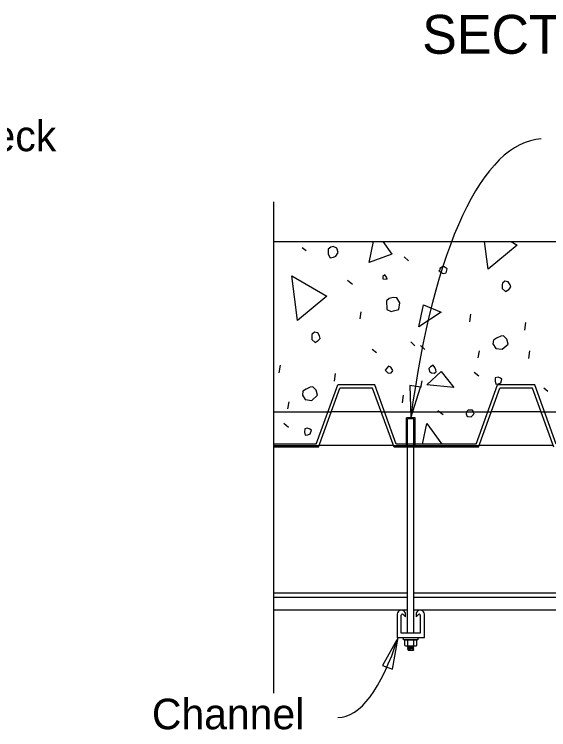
# Model space of a CAD drawing. Extents: x 112544 to 112597.1, y 111084 to 111107.1.
# Drawn here: x 112556.46 to 112559.102, y 111092.028 to 111095.563 of the extents above; entities that cross this region are included whole.
import ezdxf

# ---------------------------------------------------------------- set-up
doc = ezdxf.new("R2010")
doc.units = 0
for name, color, linetype in [('Dimension', 7, 'Continuous'), ('Lighting', 7, 'Continuous'), ('Miscellaneous', 7, 'Continuous'), ('SteelGirder', 7, 'Continuous'), ('SteelGirder_h', 7, 'Continuous'), ('SupstrConc', 7, 'Continuous'), ('TextStructures', 7, 'Continuous')]:
    doc.layers.add(name, color=color, linetype=linetype)

msp = doc.modelspace()

# ---------------------------------------------------------------- linework, layer by layer
at = {"layer": 'Dimension'}
msp.add_lwpolyline([(112557.7434, 111092.2077), (112557.7434, 111094.6352)], dxfattribs=at)
for points in [[(112558.4199, 111093.5693), (112558.4676, 111093.7204), (112558.4152, 111093.7277)], [(112558.3574, 111092.4831), (112558.2792, 111092.3454), (112558.3289, 111092.3273)]]:
    msp.add_lwpolyline(points, close=True, dxfattribs=at)
for centre, major_axis, ratio, start_param, end_param in [((112559.2223, 111092.0282), (0.1574, -2.9184), 0.2923, 3.141622, 4.140363), ((112558.0464, 111093.7554), (-0.0129, 1.6676), 0.280094, 3.141615, 3.84244)]:
    msp.add_ellipse(centre, major_axis=major_axis, ratio=ratio, start_param=start_param, end_param=end_param, dxfattribs=at)
at = {"layer": 'Lighting'}
for p, q in [((112558.4043, 111092.7018), (112557.7434, 111092.7018)), ((112559.1907, 111092.7018), (112558.4355, 111092.7018)), ((112558.4043, 111092.681), (112557.7434, 111092.681)), ((112559.2211, 111092.681), (112558.4355, 111092.681)), ((112558.4043, 111092.6185), (112557.7434, 111092.6185)), ((112558.3522, 111092.5977), (112558.3522, 111092.4831)), ((112558.373, 111092.5039), (112558.373, 111092.5929)), ((112558.3819, 111092.5966), (112558.3938, 111092.5847)), ((112558.3938, 111092.6026), (112558.3917, 111092.6069)), ((112558.3938, 111092.5847), (112558.3938, 111092.6026)), ((112560.3522, 111092.6185), (112558.4355, 111092.6185)), ((112558.4481, 111092.6069), (112558.446, 111092.6026)), ((112558.446, 111092.6026), (112558.446, 111092.5847)), ((112558.446, 111092.5847), (112558.4579, 111092.5966)), ((112558.4668, 111092.5929), (112558.4668, 111092.5039)), ((112558.4876, 111092.4831), (112558.4876, 111092.5977)), ((112558.4668, 111092.5039), (112558.373, 111092.5039)), ((112558.3522, 111092.4831), (112558.4876, 111092.4831))]:
    msp.add_line(p, q, dxfattribs=at)
for centre, radius, start, end in [((112558.373, 111092.5977), 0.0208, 26.1794, 179.9999), ((112558.3782, 111092.5929), 0.0052, 45, 180), ((112558.4668, 111092.5977), 0.0208, 0.0001, 153.8206), ((112558.4616, 111092.5929), 0.0052, 360, 135)]:
    msp.add_arc(centre, radius, start, end, dxfattribs=at)
at = {"layer": 'Miscellaneous'}
for p, q in [((112557.8828, 111094.4109), (112557.9025, 111094.3954)), ((112558.3869, 111094.3648), (112558.4079, 111094.3445)), ((112558.1075, 111094.2485), (112558.1309, 111094.2289)), ((112558.1689, 111094.0579), (112558.175, 111094.0932)), ((112558.7113, 111094.0428), (112558.7167, 111094.0805)), ((112558.9837, 111094.0019), (112558.9891, 111094.0396)), ((112558.4195, 111093.9439), (112558.4404, 111093.9236)), ((112558.2296, 111093.9085), (112558.25, 111093.8907)), ((112558.4683, 111093.9259), (112558.4892, 111093.9056)), ((112558.7537, 111093.8652), (112558.7598, 111093.9005)), ((112559.003, 111093.8621), (112559.0084, 111093.8998)), ((112557.7695, 111093.7904), (112557.775, 111093.8281)), ((112558.7337, 111093.7951), (112558.757, 111093.7755)), ((112558.0419, 111093.7495), (112558.0473, 111093.7872)), ((112557.9525, 111093.4391), (112558.0587, 111093.7309)), ((112558.242, 111093.7309), (112558.0587, 111093.7309)), ((112558.3482, 111093.4391), (112558.242, 111093.7309)), ((112558.47, 111093.7167), (112558.4761, 111093.752)), ((112558.7429, 111093.4391), (112558.8491, 111093.7309)), ((112559.0324, 111093.7309), (112558.8491, 111093.7309)), ((112559.1386, 111093.4391), (112559.0324, 111093.7309)), ((112557.9634, 111093.4235), (112558.0696, 111093.7153)), ((112558.2311, 111093.7153), (112558.0696, 111093.7153)), ((112558.3373, 111093.4235), (112558.2311, 111093.7153)), ((112558.7539, 111093.4235), (112558.86, 111093.7153)), ((112559.0215, 111093.7153), (112558.86, 111093.7153)), ((112559.1277, 111093.4235), (112559.0215, 111093.7153)), ((112559.0782, 111093.7166), (112559.0979, 111093.7012)), ((112558.3784, 111093.643), (112558.3839, 111093.6807)), ((112557.8119, 111093.6128), (112557.818, 111093.6481)), ((112558.5543, 111093.6047), (112558.5801, 111093.5857)), ((112557.7919, 111093.5428), (112557.8153, 111093.5231)), ((112557.9525, 111093.4391), (112557.7434, 111093.4391)), ((112557.9634, 111093.4235), (112557.7434, 111093.4235)), ((112558.7539, 111093.4235), (112558.3373, 111093.4235)), ((112558.7429, 111093.4391), (112558.3482, 111093.4391))]:
    msp.add_line(p, q, dxfattribs=at)
for points in [[(112558.2134, 111094.3364), (112558.2352, 111094.4392)], [(112558.2809, 111094.4392), (112558.3267, 111094.3771), (112558.2134, 111094.3364)], [(112558.8022, 111094.3026), (112558.7848, 111094.4392)], [(112558.9163, 111094.4392), (112558.9463, 111094.4215), (112558.8022, 111094.3026)], [(112558.0121, 111094.4015), (112558.0107, 111094.3779), (112558.0207, 111094.3598), (112558.0383, 111094.3619), (112558.0497, 111094.3676), (112558.0603, 111094.386), (112558.0545, 111094.4077), (112558.0368, 111094.4159), (112558.0247, 111094.4127), (112558.0121, 111094.4015)], [(112558.5616, 111094.2925), (112558.5799, 111094.2819), (112558.5944, 111094.2858), (112558.5996, 111094.3053), (112558.5805, 111094.3183), (112558.5722, 111094.3109), (112558.5632, 111094.3059), (112558.5616, 111094.2925), (112558.5603, 111094.2974)], [(112557.8604, 111094.0503), (112557.8324, 111094.2706), (112558.0045, 111094.1691), (112557.8604, 111094.0503)], [(112558.2814, 111094.2563), (112558.3027, 111094.2542), (112558.3001, 111094.2639), (112558.292, 111094.2746), (112558.2812, 111094.2666), (112558.2814, 111094.2563)], [(112558.872, 111094.2256), (112558.8717, 111094.2074), (112558.8883, 111094.1937), (112558.9039, 111094.2031), (112558.914, 111094.2135), (112558.9108, 111094.2256), (112558.9014, 111094.2412), (112558.885, 111094.2446), (112558.8724, 111094.2335), (112558.872, 111094.2256)], [(112558.3002, 111094.1474), (112558.3016, 111094.1038), (112558.3223, 111094.0938), (112558.3344, 111094.0971), (112558.361, 111094.1042), (112558.3653, 111094.1364), (112558.3509, 111094.161), (112558.3321, 111094.1637), (112558.3128, 111094.1586), (112558.3002, 111094.1474)], [(112558.4588, 111094.0191), (112558.4819, 111094.1262), (112558.5692, 111094.0901), (112558.4588, 111094.0191)], [(112557.9302, 111093.9732), (112557.9299, 111093.955), (112557.9465, 111093.9414), (112557.9621, 111093.9507), (112557.9722, 111093.9612), (112557.969, 111093.9733), (112557.9596, 111093.9889), (112557.9432, 111093.9922), (112557.9307, 111093.9811), (112557.9302, 111093.9732)], [(112558.8259, 111093.9337), (112558.8397, 111093.9115), (112558.8719, 111093.9072), (112558.9012, 111093.9332), (112558.8947, 111093.9573), (112558.8774, 111093.9734), (112558.8647, 111093.9726), (112558.8443, 111093.9619), (112558.8287, 111093.9526), (112558.8259, 111093.9337)], [(112558.5129, 111093.7981), (112558.5227, 111093.7904), (112558.5361, 111093.7888), (112558.5445, 111093.7962), (112558.5443, 111093.8065), (112558.5386, 111093.8179), (112558.5306, 111093.8287), (112558.5174, 111093.82), (112558.509, 111093.8126), (112558.5129, 111093.7981)], [(112558.2939, 111093.8041), (112558.3081, 111093.7898), (112558.3232, 111093.7912), (112558.3309, 111093.8011), (112558.3296, 111093.8059), (112558.3209, 111093.8191), (112558.3093, 111093.8238), (112558.3016, 111093.8139), (112558.2939, 111093.8041)], [(112558.4994, 111093.7324), (112558.5699, 111093.7978), (112558.6325, 111093.7188), (112558.4994, 111093.7324)], [(112558.8363, 111093.7501), (112558.8402, 111093.7357), (112558.8529, 111093.7365), (112558.8643, 111093.7421), (112558.8701, 111093.7592), (112558.8633, 111093.7652), (112558.8517, 111093.7698), (112558.8373, 111093.7659), (112558.8363, 111093.7501)], [(112557.8842, 111093.6814), (112557.8979, 111093.6592), (112557.9301, 111093.6549), (112557.9594, 111093.6808), (112557.9529, 111093.705), (112557.9357, 111093.721), (112557.9229, 111093.7202), (112557.9025, 111093.7096), (112557.8869, 111093.7002), (112557.8842, 111093.6814)], [(112558.6961, 111093.578), (112558.7022, 111093.5745), (112558.718, 111093.5735), (112558.7305, 111093.5846), (112558.7334, 111093.5932), (112558.7247, 111093.6064), (112558.7041, 111093.606), (112558.6957, 111093.5986), (112558.6935, 111093.5876), (112558.6961, 111093.578)], [(112557.8945, 111093.4978), (112557.8984, 111093.4833), (112557.9111, 111093.4841), (112557.9226, 111093.4898), (112557.9283, 111093.5069), (112557.9216, 111093.5128), (112557.91, 111093.5175), (112557.8955, 111093.5136), (112557.8945, 111093.4978)], [(112558.4775, 111093.4391), (112558.499, 111093.5407), (112558.574, 111093.4391)]]:
    msp.add_lwpolyline(points, dxfattribs=at)
at = {"layer": 'SteelGirder'}
for p, q in [((112558.2738, 111093.5979), (112558.0269, 111093.5979)), ((112559.0642, 111093.5979), (112558.8173, 111093.5979)), ((112558.4407, 111093.5693), (112558.3991, 111093.5693)), ((112558.3991, 111093.4235), (112558.3991, 111093.5693)), ((112558.4043, 111092.5039), (112558.4043, 111093.5641)), ((112558.4355, 111093.5641), (112558.4043, 111093.5641)), ((112558.4355, 111092.5039), (112558.4355, 111093.5641)), ((112558.4407, 111093.4235), (112558.4407, 111093.5693)), ((112558.3345, 111093.4312), (112557.9662, 111093.4312)), ((112559.1249, 111093.4312), (112558.7566, 111093.4312)), ((112558.3898, 111092.4436), (112558.3898, 111092.472)), ((112558.3898, 111092.472), (112558.45, 111092.472)), ((112558.4048, 111092.4436), (112558.4048, 111092.472)), ((112558.4349, 111092.4436), (112558.4349, 111092.472)), ((112558.45, 111092.4436), (112558.45, 111092.472)), ((112558.3973, 111092.4414), (112558.4424, 111092.4414)), ((112558.4042, 111092.4408), (112558.4108, 111092.4414)), ((112558.4042, 111092.4408), (112558.4053, 111092.4414)), ((112558.4095, 111092.4386), (112558.4042, 111092.4408)), ((112558.4042, 111092.4356), (112558.4095, 111092.4386)), ((112558.4042, 111092.4356), (112558.4355, 111092.4383)), ((112558.4095, 111092.4334), (112558.4042, 111092.4356)), ((112558.4042, 111092.4305), (112558.4095, 111092.4334)), ((112558.4042, 111092.4305), (112558.4355, 111092.4331)), ((112558.4095, 111092.4283), (112558.4042, 111092.4305)), ((112558.4042, 111092.4253), (112558.4095, 111092.4283)), ((112558.4042, 111092.4253), (112558.4355, 111092.428)), ((112558.4095, 111092.4231), (112558.4042, 111092.4253)), ((112558.406, 111092.4211), (112558.4095, 111092.4231)), ((112558.4061, 111092.4211), (112558.4326, 111092.4211)), ((112558.4161, 111092.4211), (112558.4355, 111092.4228)), ((112558.4302, 111092.4405), (112558.4318, 111092.4414)), ((112558.4355, 111092.4383), (112558.4302, 111092.4405)), ((112558.4302, 111092.4353), (112558.4355, 111092.4383)), ((112558.4355, 111092.4331), (112558.4302, 111092.4353)), ((112558.4302, 111092.4301), (112558.4355, 111092.4331)), ((112558.4355, 111092.428), (112558.4302, 111092.4301)), ((112558.4302, 111092.4249), (112558.4355, 111092.428)), ((112558.4355, 111092.4228), (112558.4302, 111092.4249)), ((112558.4326, 111092.4211), (112558.4355, 111092.4228))]:
    msp.add_line(p, q, dxfattribs=at)
msp.add_lwpolyline([(112558.4552, 111092.4831), (112558.4552, 111092.472), (112558.3846, 111092.472), (112558.3846, 111092.4831)], close=True, dxfattribs=at)
for centre, radius, start, end in [((112558.3973, 111092.4552), 0.0138, 236.9791, 303.0209), ((112558.4199, 111092.4933), 0.0519, 253.1396, 286.8604), ((112558.4424, 111092.4552), 0.0138, 236.9791, 303.0209)]:
    msp.add_arc(centre, radius, start, end, dxfattribs=at)
at = {"layer": 'SteelGirder_h'}
for p, q in [((112557.7434, 111093.5979), (112558.0269, 111093.5979)), ((112558.2738, 111093.5979), (112558.8173, 111093.5979)), ((112559.0642, 111093.5979), (112559.6078, 111093.5979)), ((112557.7434, 111093.4312), (112557.9662, 111093.4312)), ((112558.3345, 111093.4312), (112558.7566, 111093.4312))]:
    msp.add_line(p, q, dxfattribs=at)
at = {"layer": 'SupstrConc'}
msp.add_line((112557.7434, 111094.4392), (112564.7526, 111094.4392), dxfattribs=at)

# ---------------------------------------------------------------- texts
at = {"layer": 'TextStructures'}
for s, height, p in [('SECTION A-A', 0.192, (112558.4762, 111095.3677)), ('Bridge Deck', 0.1512, (112555.5657, 111094.8861)), ('Channel', 0.1512, (112557.1401, 111092.0297))]:
    msp.add_text(s, height=height, dxfattribs=at).set_placement(p)

doc.saveas('drawing.dxf')
